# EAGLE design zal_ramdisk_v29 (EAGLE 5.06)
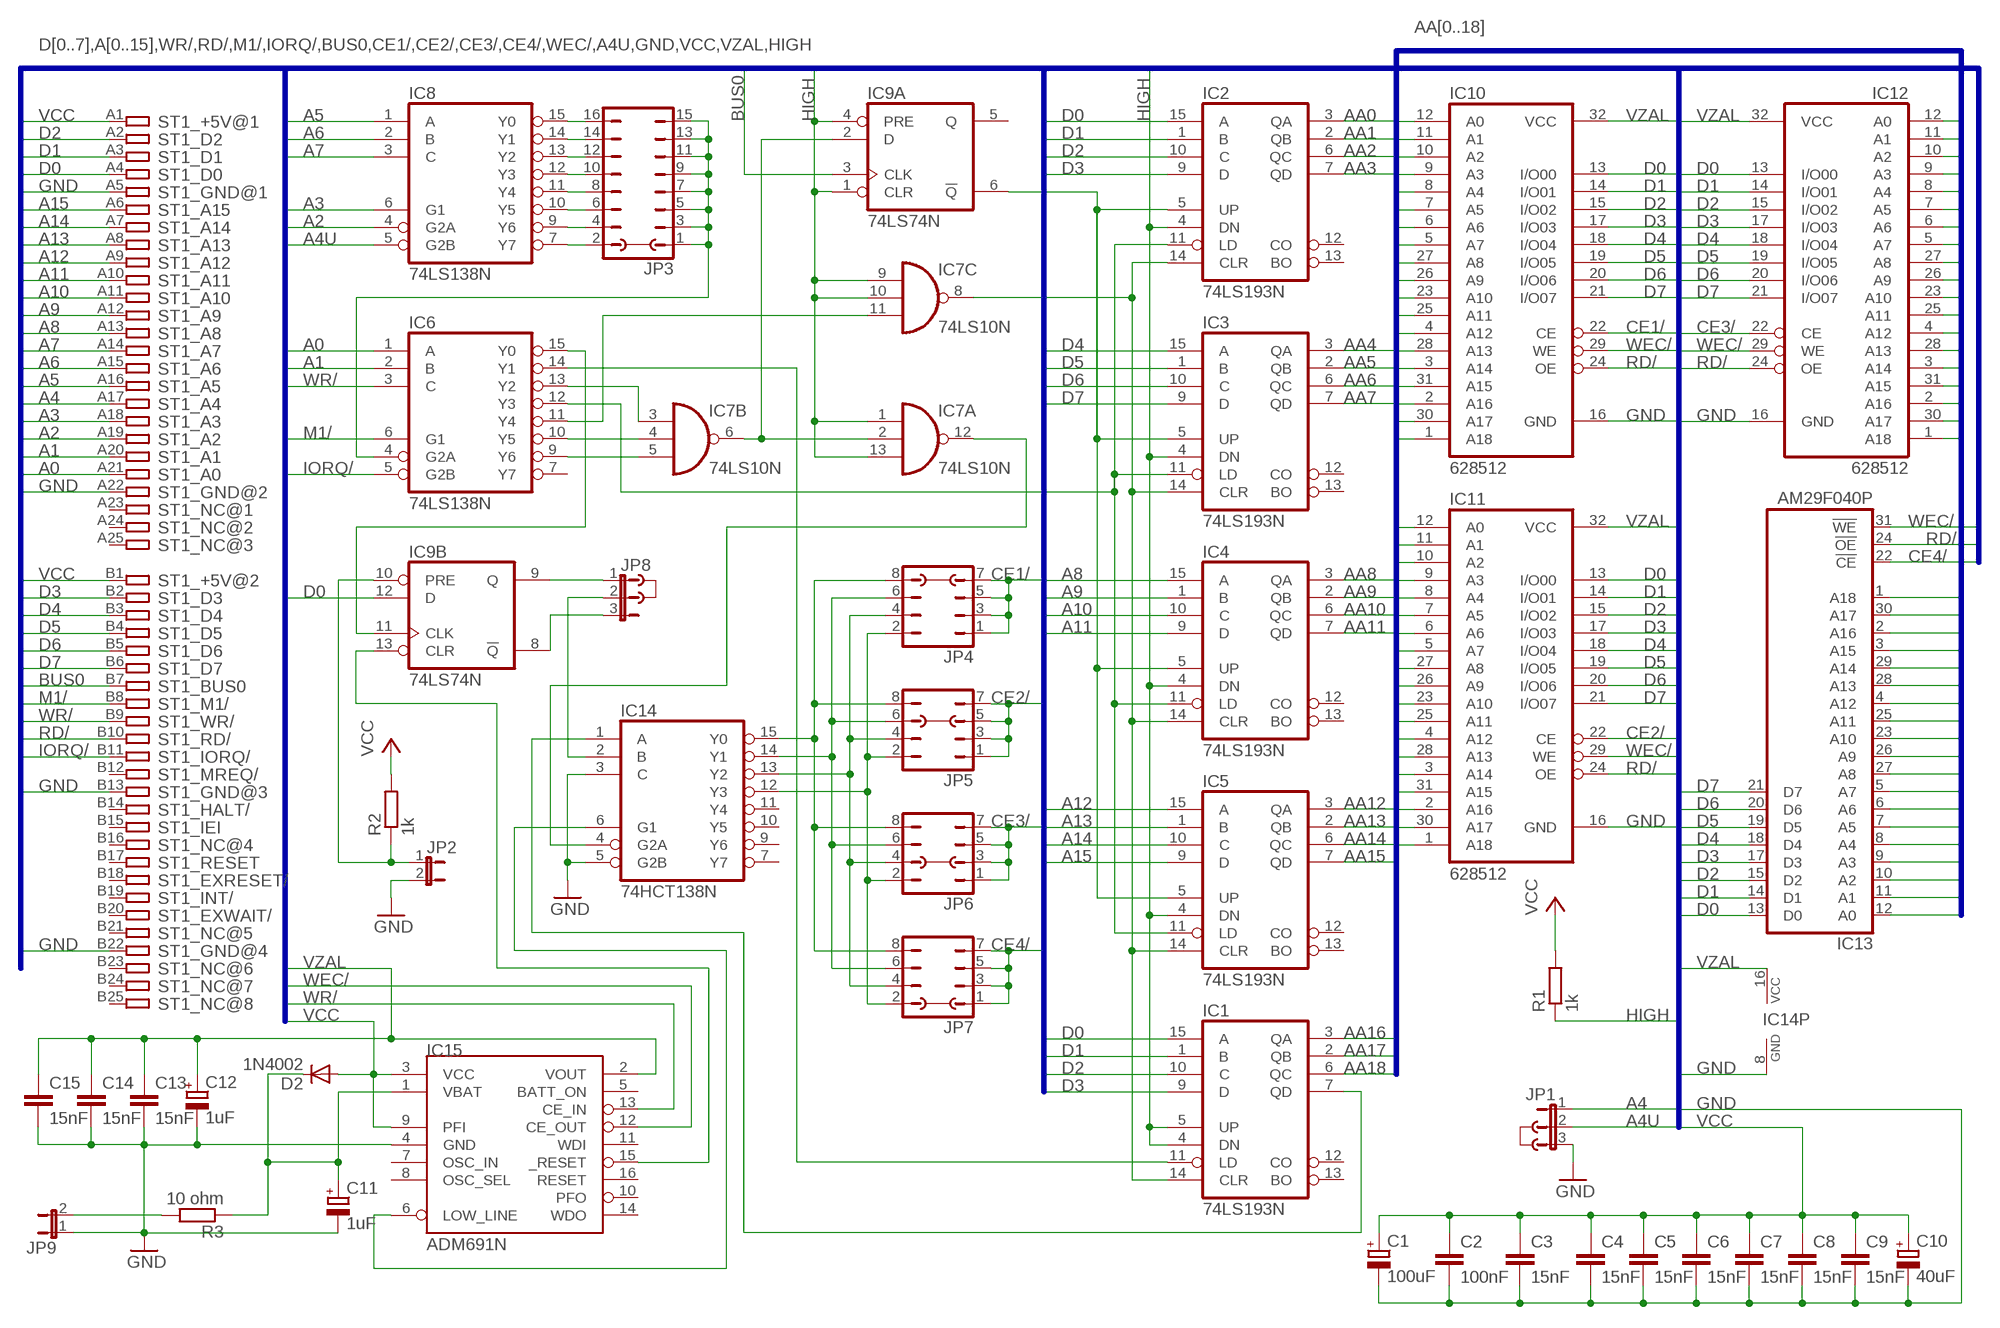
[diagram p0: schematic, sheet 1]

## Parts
C1  100uF  CPOL-EUE2-5  [E2-5]
C2  100nF  C-EU050-024X044  [C050-024X044]
C3  15nF  C-EU050-024X044  [C050-024X044]
C4  15nF  C-EU050-024X044  [C050-024X044]
C5  15nF  C-EU050-024X044  [C050-024X044]
C6  15nF  C-EU050-024X044  [C050-024X044]
C7  15nF  C-EU050-024X044  [C050-024X044]
C8  15nF  C-EU050-024X044  [C050-024X044]
C9  15nF  C-EU050-024X044  [C050-024X044]
C10  40uF  CPOL-EUE2-5  [E2-5]
C11  1uF  CPOL-EUE2-5  [E2-5]
C12  1uF  CPOL-EUE2-5  [E2-5]
C13  15nF  C-EU050-024X044  [C050-024X044]
C14  15nF  C-EU050-024X044  [C050-024X044]
C15  15nF  C-EU050-024X044  [C050-024X044]
D2  1N4002  DIODE-DO41-10  [DO41-10]
IC1  74LS193N  [DIL16]
IC2  74LS193N  [DIL16]
IC3  74LS193N  [DIL16]
IC4  74LS193N  [DIL16]
IC5  74LS193N  [DIL16]
IC6  74LS138N  [DIL16]
IC7  74LS10N  [DIL14]
IC8  74LS138N  [DIL16]
IC9  74LS74N  [DIL14]
IC10  628512  [DIL32]
IC11  628512  [DIL32]
IC12  628512  [DIL32]
IC13  AM29F040P  [DIL32]
IC14  74HCT138N  [DIL16]
IC15  ADM691N  [DIL16]
J1  JUMP-Q  [JUMP]
J3  JUMPER  [JUMP]
J4  JUMP-Q  [JUMP]
J5  JUMP-Q  [JUMP]
J6  JUMP-Q  [JUMP]
J7  JUMP-Q  [JUMP]
J8  JUMPER  [JUMP]
JP1  JP2E  [JP2]
JP2  JP1E  [JP1]
JP3  JP8Q  [JP8Q]
JP4  JP4Q  [JP4Q]
JP5  JP4Q  [JP4Q]
JP6  JP4Q  [JP4Q]
JP7  JP4Q  [JP4Q]
JP8  JP2E  [JP2]
JP9  JP1E  [JP1]
R1  1k  R-EU_0207/7  [0207/7]
R2  1k  R-EU_0207/7  [0207/7]
R3  10 ohm  R-EU_0207/7  [0207/7]
ST1  MZ800BUS  [MZ800BUS]

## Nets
A0: IC6.1(A) ST1.A21
A1: IC6.2(B) ST1.A20
A2: IC8.4(G2A) ST1.A19
A3: IC8.6(G1) ST1.A18
A4: JP1.1 ST1.A17
A4U: IC8.5(G2B) JP1.2
A5: IC8.1(A) ST1.A16
A6: IC8.2(B) ST1.A15
A7: IC8.3(C) ST1.A14
A8: IC4.15(A) ST1.A13
A9: IC4.1(B) ST1.A12
A10: IC4.10(C) ST1.A11
A11: IC4.9(D) ST1.A10
A12: IC5.15(A) ST1.A9
A13: IC5.1(B) ST1.A8
A14: IC5.10(C) ST1.A7
A15: IC5.9(D) ST1.A6
AA0: IC2.3(QA) IC10.12(A0) IC11.12(A0) IC12.12(A0) IC13.12(A0)
AA1: IC2.2(QB) IC10.11(A1) IC11.11(A1) IC12.11(A1) IC13.11(A1)
AA2: IC2.6(QC) IC10.10(A2) IC11.10(A2) IC12.10(A2) IC13.10(A2)
AA3: IC2.7(QD) IC10.9(A3) IC11.9(A3) IC12.9(A3) IC13.9(A3)
AA4: IC3.3(QA) IC10.8(A4) IC11.8(A4) IC12.8(A4) IC13.8(A4)
AA5: IC3.2(QB) IC10.7(A5) IC11.7(A5) IC12.7(A5) IC13.7(A5)
AA6: IC3.6(QC) IC10.6(A6) IC11.6(A6) IC12.6(A6) IC13.6(A6)
AA7: IC3.7(QD) IC10.5(A7) IC11.5(A7) IC12.5(A7) IC13.5(A7)
AA8: IC4.3(QA) IC10.27(A8) IC11.27(A8) IC12.27(A8) IC13.27(A8)
AA9: IC4.2(QB) IC10.26(A9) IC11.26(A9) IC12.26(A9) IC13.26(A9)
AA10: IC4.6(QC) IC10.23(A10) IC11.23(A10) IC12.23(A10) IC13.23(A10)
AA11: IC4.7(QD) IC10.25(A11) IC11.25(A11) IC12.25(A11) IC13.25(A11)
AA12: IC5.3(QA) IC10.4(A12) IC11.4(A12) IC12.4(A12) IC13.4(A12)
AA13: IC5.2(QB) IC10.28(A13) IC11.28(A13) IC12.28(A13) IC13.28(A13)
AA14: IC5.6(QC) IC10.3(A14) IC11.3(A14) IC12.3(A14) IC13.29(A14)
AA15: IC5.7(QD) IC10.31(A15) IC11.31(A15) IC12.31(A15) IC13.3(A15)
AA16: IC1.3(QA) IC10.2(A16) IC11.2(A16) IC12.2(A16) IC13.2(A16)
AA17: IC1.2(QB) IC10.30(A17) IC11.30(A17) IC12.30(A17) IC13.30(A17)
AA18: IC1.6(QC) IC10.1(A18) IC11.1(A18) IC12.1(A18) IC13.1(A18)
BAT3V: C11.+ D2.C IC15.1(VBAT) R3.1
BUS0: IC9.3(A:CLK) ST1.B7
CE1/: IC10.22(CE) JP4.1 JP4.3 JP4.5 JP4.7
CE2/: IC11.22(CE) JP5.1 JP5.3 JP5.5 JP5.7
CE3/: IC12.22(CE) JP6.1 JP6.3 JP6.5 JP6.7
CE4/: IC13.22(!CE) JP7.1 JP7.3 JP7.5 JP7.7
D0: IC1.15(A) IC2.15(A) IC9.12(B:D) IC10.13(I/O00) IC11.13(I/O00) IC12.13(I/O00) IC13.13(D0) ST1.A4
D1: IC1.1(B) IC2.1(B) IC10.14(I/O01) IC11.14(I/O01) IC12.14(I/O01) IC13.14(D1) ST1.A3
D2: IC1.10(C) IC2.10(C) IC10.15(I/O02) IC11.15(I/O02) IC12.15(I/O02) IC13.15(D2) ST1.A2
D3: IC1.9(D) IC2.9(D) IC10.17(I/O03) IC11.17(I/O03) IC12.17(I/O03) IC13.17(D3) ST1.B2
D4: IC3.15(A) IC10.18(I/O04) IC11.18(I/O04) IC12.18(I/O04) IC13.18(D4) ST1.B3
D5: IC3.1(B) IC10.19(I/O05) IC11.19(I/O05) IC12.19(I/O05) IC13.19(D5) ST1.B4
D6: IC3.10(C) IC10.20(I/O06) IC11.20(I/O06) IC12.20(I/O06) IC13.20(D6) ST1.B5
D7: IC3.9(D) IC10.21(I/O07) IC11.21(I/O07) IC12.21(I/O07) IC13.21(D7) ST1.B6
EEE: IC14.2(B) JP8.2
GND [power]: C1.- C2.2 C3.2 C4.2 C5.2 C6.2 C7.2 C8.2 C9.2 C10.- C11.- C12.- C13.2 C14.2 C15.2 IC10.16(GND) IC11.16(GND) IC12.16(GND) IC14.3(C) IC14.5(G2B) IC14.8(GND) IC15.4(GND) JP1.3 JP2.2 JP9.1 ST1.A5 ST1.A22 ST1.B13 ST1.B22
HIGH: IC1.4(DN) IC1.5(UP) IC2.4(DN) IC3.4(DN) IC4.4(DN) IC5.4(DN) IC7.1(A:I0) IC7.9(C:I0) IC7.10(C:I1) IC7.13(A:I2) IC9.1(A:CLR) IC9.4(A:PRE) R1.1
IORQ/: IC6.5(G2B) ST1.B11
M1/: IC6.6(G1) ST1.B8
N$1: IC6.10(Y5) IC7.4(B:I1)
N$2: IC6.9(Y6) IC7.5(B:I2)
N$3: IC6.4(G2A) JP3.1 JP3.3 JP3.5 JP3.7 JP3.9 JP3.11 JP3.13 JP3.15
N$4: IC6.13(Y2) IC7.3(B:I0)
N$5: IC6.11(Y4) IC7.11(C:I2)
N$6: IC7.2(A:I1) IC7.6(B:O) IC9.2(A:D)
N$7: IC8.15(Y0) JP3.16
N$8: IC1.11(LD) IC6.14(Y1)
N$9: IC1.7(QD) IC14.1(A)
N$11: JP9.2 R3.2
N$24: IC2.5(UP) IC3.5(UP) IC4.5(UP) IC5.5(UP) IC9.6(A:!Q)
N$25: IC1.14(CLR) IC2.14(CLR) IC3.14(CLR) IC4.14(CLR) IC5.14(CLR) IC7.8(C:O)
N$26: IC2.11(LD) IC3.11(LD) IC4.11(LD) IC5.11(LD) IC6.12(Y3)
N$31: IC9.9(B:Q) JP8.1
N$34: IC9.13(B:CLR) IC15.15(_RESET)
N$36: IC14.6(G1) IC15.6(LOW_LINE)
N$37: IC6.15(Y0) IC9.11(B:CLK)
N$38: IC7.12(A:O) IC14.4(G2A)
N$39: IC8.14(Y1) JP3.14
N$40: IC8.13(Y2) JP3.12
N$41: IC8.12(Y3) JP3.10
N$42: IC8.11(Y4) JP3.8
N$43: IC8.10(Y5) JP3.6
N$44: IC8.9(Y6) JP3.4
N$45: IC8.7(Y7) JP3.2
N$47: IC9.10(B:PRE) JP2.1 R2.1
N$52: IC14.14(Y1) JP4.6 JP5.6 JP6.6 JP7.6
N$53: IC14.15(Y0) JP4.8 JP5.8 JP6.8 JP7.8
N$54: IC14.13(Y2) JP4.4 JP5.4 JP6.4 JP7.4
N$55: IC14.12(Y3) JP4.2 JP5.2 JP6.2 JP7.2
N$56: IC9.8(B:!Q) JP8.3
RD/: IC10.24(OE) IC11.24(OE) IC12.24(OE) IC13.24(!OE) ST1.B10
VCC [power]: C1.+ C2.1 C3.1 C4.1 C5.1 C6.1 C7.1 C8.1 C9.1 C10.+ D2.A IC15.3(VCC) IC15.9(PFI) R1.2 R2.2 ST1.A1 ST1.B1
VZAL [power]: C12.+ C13.1 C14.1 C15.1 IC10.32(VCC) IC11.32(VCC) IC12.32(VCC) IC14.16(VCC) IC15.2(VOUT)
WEC/: IC10.29(WE) IC11.29(WE) IC12.29(WE) IC13.31(!WE) IC15.12(CE_OUT)
WR/: IC6.3(C) IC15.13(CE_IN) ST1.B9
Unconnected: IC1.12(CO) IC1.13(BO) IC2.12(CO) IC2.13(BO) IC3.12(CO) IC3.13(BO) IC4.12(CO) IC4.13(BO) IC5.12(CO) IC5.13(BO) IC6.7(Y7) IC9.5(A:Q) IC14.7(Y7) IC14.9(Y6) IC14.10(Y5) IC14.11(Y4) IC15.5(BATT_ON) IC15.7(OSC_IN) IC15.8(OSC_SEL) IC15.10(PFO) IC15.11(WDI) IC15.14(WDO) IC15.16(RESET) ST1.A23 ST1.A24 ST1.A25 ST1.B12 ST1.B14 ST1.B15 ST1.B16 ST1.B17 ST1.B18 ST1.B19 ST1.B20 ST1.B21 ST1.B23 ST1.B24 ST1.B25

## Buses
D[0..7],A[0..15],WR/,RD/,M1/,IORQ/,BUS0,CE1/,CE2/,CE3/,CE4/,WEC/,A4U,GND,VCC,VZAL,HIGH
AA[0..18]

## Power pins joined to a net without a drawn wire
GND: IC1.8(GND) IC2.8(GND) IC3.8(GND) IC4.8(GND) IC5.8(GND) IC6.8(GND) IC7.7(P:GND) IC8.8(GND) IC9.7(P:GND) IC13.16(GND)
VCC: IC1.16(VCC) IC2.16(VCC) IC3.16(VCC) IC4.16(VCC) IC5.16(VCC) IC6.16(VCC) IC7.14(P:VCC) IC8.16(VCC) IC9.14(P:VCC) IC13.32(VCC)

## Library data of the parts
C1 C10-C12 = rcl:CPOL-EU: POLARIZED CAPACITOR, European symbol
C2-C9 C13-C15 = rcl:C-EU: CAPACITOR, European symbol
D2 = diode:DIODE-: DIODE
IC1-IC5 = sharp:74*193: Synchronous 4-bit UP/DOWN COUNTER
IC6 IC8 IC14 = 74xx-eu:74*138: 3-line to 8-line DECODER/DEMULTIPLEXER
IC7 = 74xx-eu:74*10: Triple 3-input NAND gate
IC9 = 74xx-eu:74*74: Dual D type positive edge triggered FLIP FLOP, preset and clear
IC10-IC12 = sharp:628512: 4M SRAM 512kword x 8bit
IC13 = sharp:AM29F040: 4-Megabit FLASH MEMORY (512 K x 8 bit) 5 V-only
IC15 = sharp:ADM691: WATCHDOG
J1 J4-J7 = jumper:JUMP-Q: JUMPER header
J3 J8 = jumper:JUMPER: JUMPER header
JP1 JP8 = jumper:JP2E: JUMPER
JP2 JP9 = jumper:JP1E: JUMPER
JP3 = jumper:JP8Q: JUMPER
JP4-JP7 = jumper:JP4Q: JUMPER
R1-R3 = rcl:R-EU_: RESISTOR, European symbol
ST1 = sharp:MZ800BUS: 50-bit BUS for MZ800

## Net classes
0 default: width 0.203 mm
1 power: width 1.143 mm, drill 0.254 mm, clearance 0.381 mm

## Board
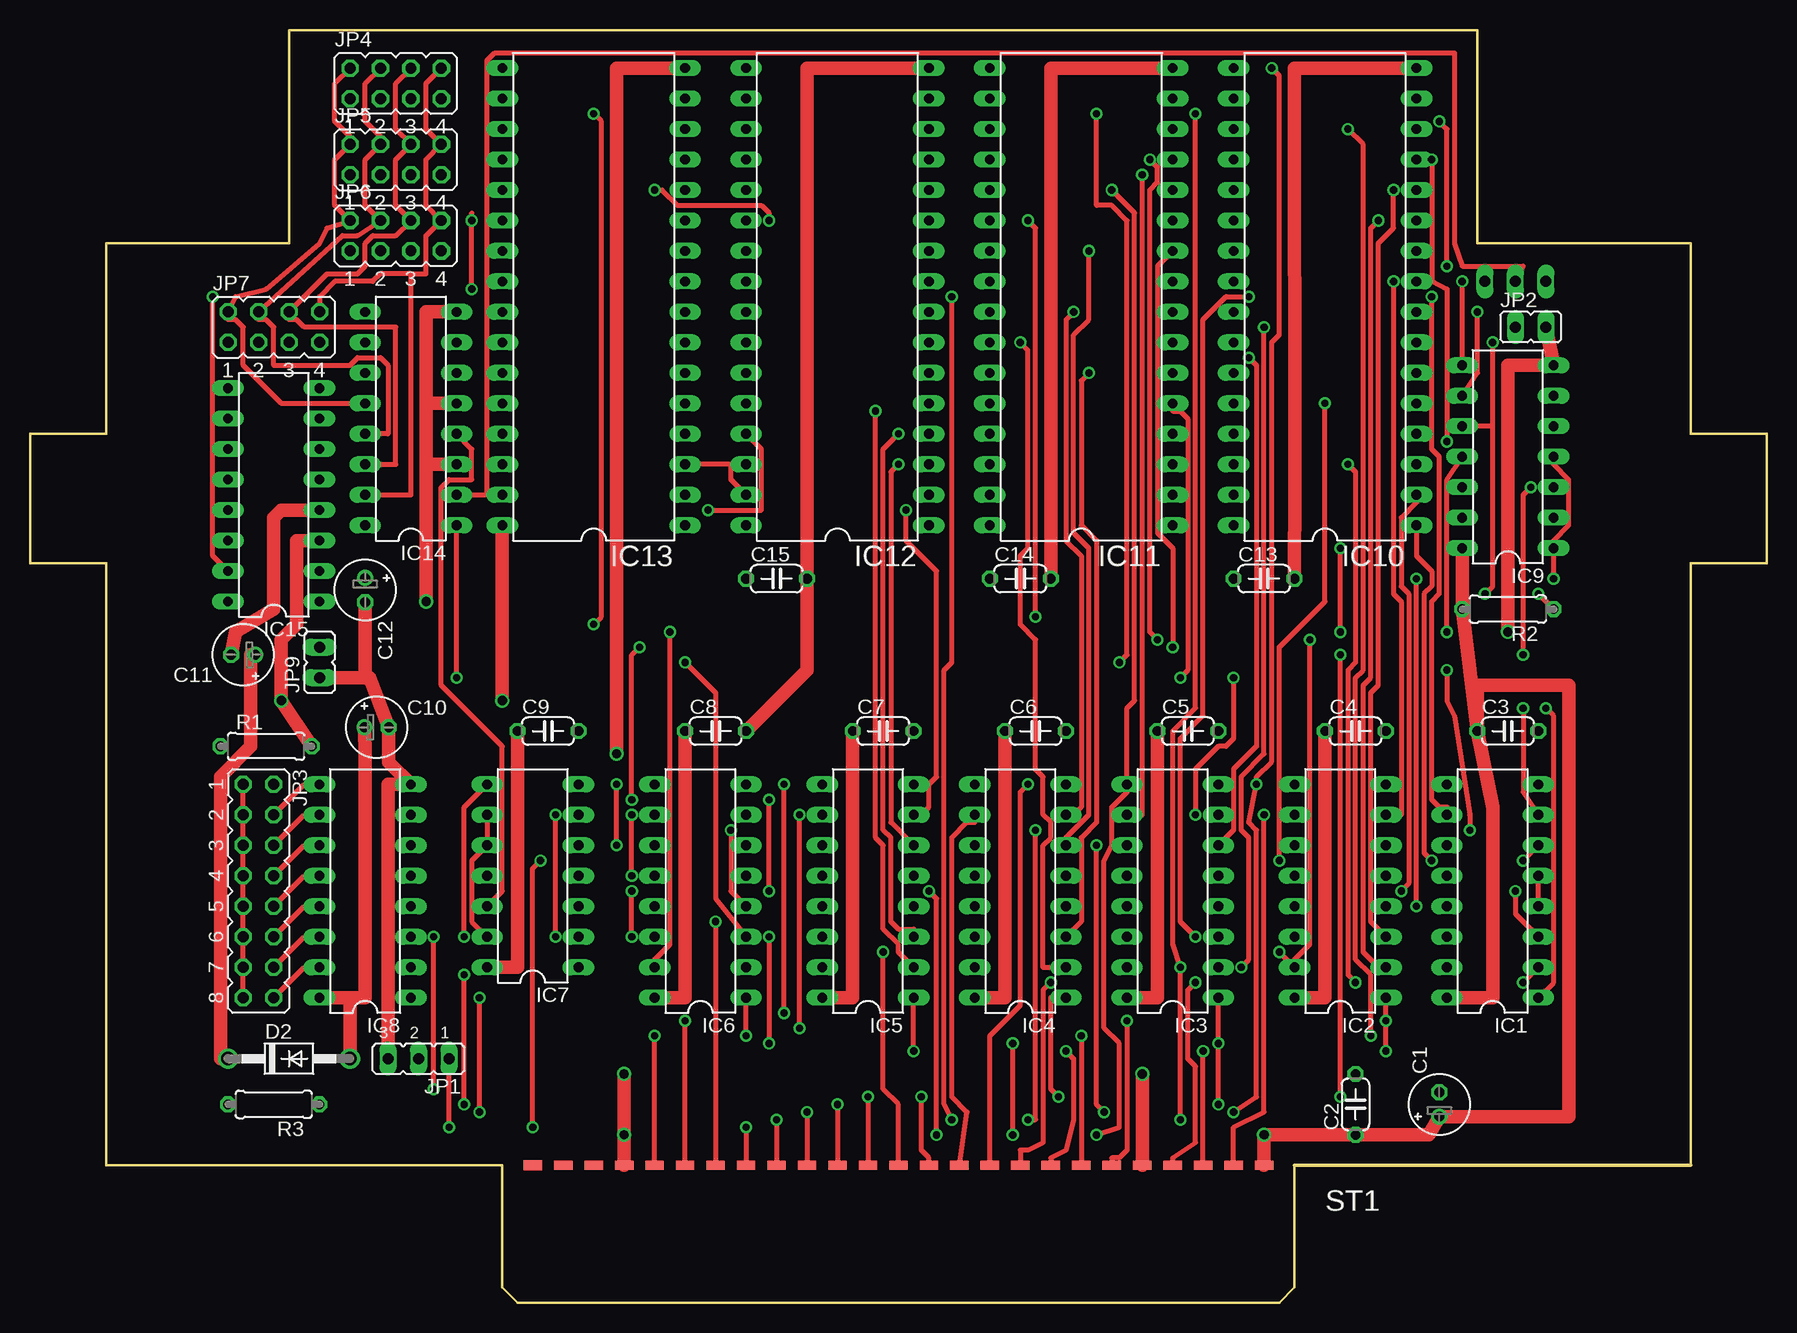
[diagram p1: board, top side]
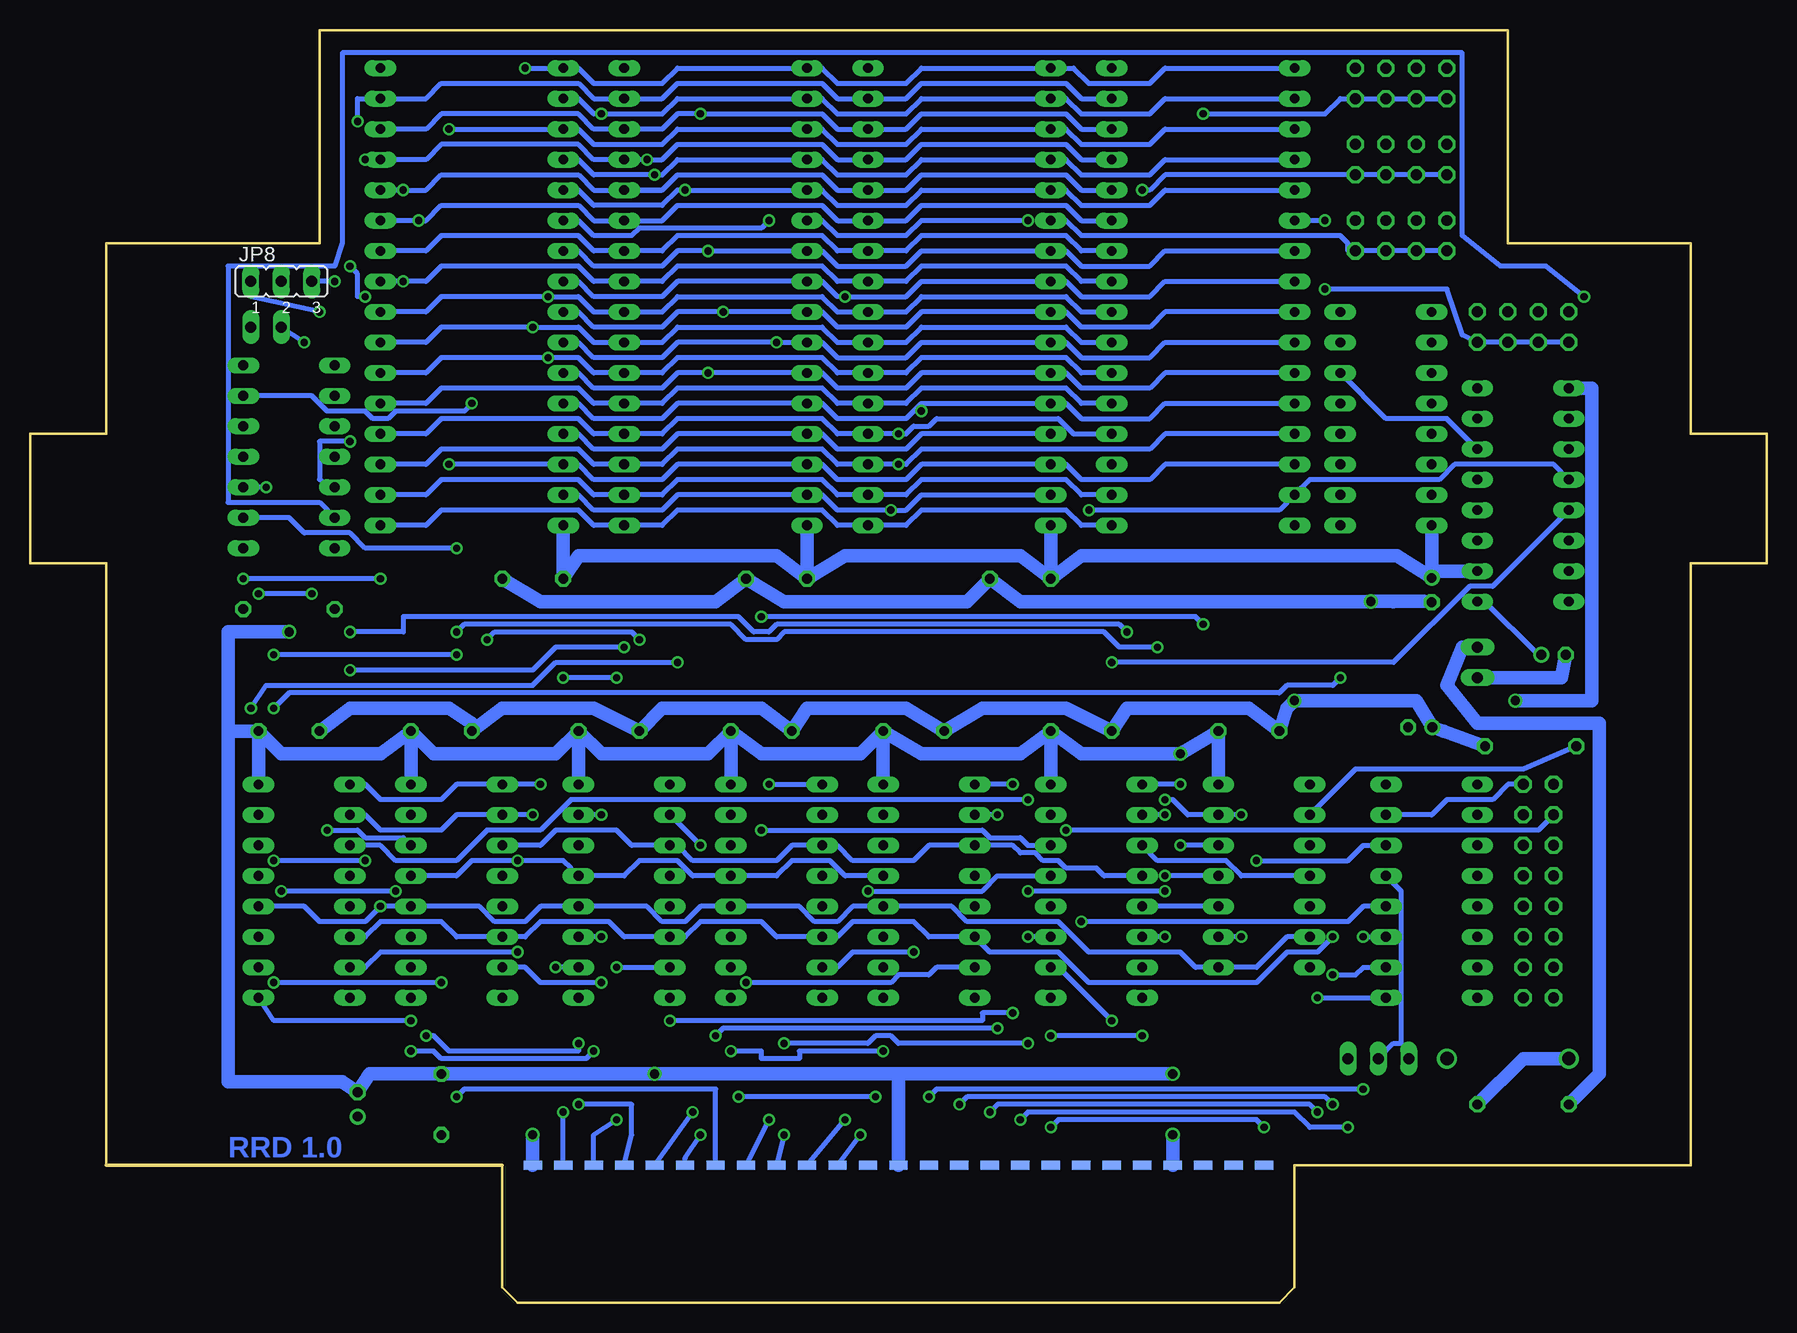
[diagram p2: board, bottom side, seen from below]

Size 144.78 x 106.05 mm. Coordinates in mm from the lower left corner, seen from the top.
Outline: 21.59,88.27 6.35,88.27 6.35,72.39 0,72.39 0,61.59 6.35,61.59 6.35,11.43 39.37,11.43 39.37,1.27 40.64,0 104.14,0 105.41,1.27 105.41,11.43 138.43,11.43 138.43,61.59 144.78,61.59 144.78,72.39 138.43,72.39 138.43,88.27 120.65,88.27 120.65,106.05 21.59,106.05 21.59,88.27
Copper layers (1*16): Top 0.035mm / dielectric 1.5mm / Bottom 0.035mm
Design rules "default *": minimum track width 10mil, minimum drill 22mil, track to track 8mil, track to pad 8mil, pad to pad 8mil, via to via 8mil, smd to smd 8mil, copper to edge 40mil, drill to drill 8mil, minimum pad ring 10mil, minimum via ring 8mil, stop-mask expansion 4mil, vias tented up to drill 0mil, thermal gap 10mil
bKeepout: area 138.4,62.2 to 144.8,72.4
tRestrict: area 38.7,2.5 to 106.7,10.8; area 6.4,11.4 to 13.3,88.3; area 0,62.2 to 6.4,72.4; area 128.9,11.4 to 138.4,88.3; area 138.4,62.2 to 144.8,72.4
bRestrict: area 38.7,2.5 to 106.7,10.8; area 6.4,11.4 to 13.3,88.3; area 0,62.2 to 6.4,72.4; area 128.9,11.4 to 138.4,88.3
vRestrict: area 40.6,10.8 to 104.8,13.3; 3 lines

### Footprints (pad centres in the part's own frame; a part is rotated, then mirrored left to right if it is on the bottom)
E2-5 = drill 0.813 pad 1.27 round: + -1.016,0 | drill 0.813 pad 1.27 octagon: - 1.016,0
C050-024X044 = drill 0.813 octagon: 1 -2.54,0; 2 2.54,0
DO41-10 = drill 1.118 round: A 5.08,0; C -5.08,0
DIL16 = drill 0.813 long: 1 -8.89,-3.81; 2 -6.35,-3.81; 3 -3.81,-3.81; 4 -1.27,-3.81; 5 1.27,-3.81; 6 3.81,-3.81; 7 6.35,-3.81; 8 8.89,-3.81; 9 8.89,3.81; 10 6.35,3.81; 11 3.81,3.81; 12 1.27,3.81; 13 -1.27,3.81; 14 -3.81,3.81; 15 -6.35,3.81; 16 -8.89,3.81
DIL14 = drill 0.813 long: 1 -7.62,-3.81; 2 -5.08,-3.81; 3 -2.54,-3.81; 4 0,-3.81; 5 2.54,-3.81; 6 5.08,-3.81; 7 7.62,-3.81; 8 7.62,3.81; 9 5.08,3.81; 10 2.54,3.81; 11 0,3.81; 12 -2.54,3.81; 13 -5.08,3.81; 14 -7.62,3.81
DIL32 = drill 0.813 long: 1 -17.78,-7.62; 2 -15.24,-7.62; 3 -12.7,-7.62; 4 -10.16,-7.62; 5 -7.62,-7.62; 6 -5.08,-7.62; 7 -2.54,-7.62; 8 0,-7.62; 9 2.54,-7.62; 10 5.08,-7.62; 11 7.62,-7.62; 12 10.16,-7.62; 13 12.7,-7.62; 14 15.24,-7.62; 15 17.78,-7.62; 16 20.32,-7.62; 17 20.32,7.62; 18 17.78,7.62; 19 15.24,7.62; 20 12.7,7.62; 21 10.16,7.62; 22 7.62,7.62; 23 5.08,7.62; 24 2.54,7.62; 25 0,7.62; 26 -2.54,7.62; 27 -5.08,7.62; 28 -7.62,7.62; 29 -10.16,7.62; 30 -12.7,7.62; 31 -15.24,7.62; 32 -17.78,7.62
JP2 = drill 0.914 long: 1 -2.54,0; 2 0,0; 3 2.54,0
JP1 = drill 0.914 long: 1 0,-1.27; 2 0,1.27
JP8Q = drill 0.914 octagon: 1 -8.89,-1.27; 2 -8.89,1.27; 3 -6.35,-1.27; 4 -6.35,1.27; 5 -3.81,-1.27; 6 -3.81,1.27; 7 -1.27,-1.27; 8 -1.27,1.27; 9 1.27,-1.27; 10 1.27,1.27; 11 3.81,-1.27; 12 3.81,1.27; 13 6.35,-1.27; 14 6.35,1.27; 15 8.89,-1.27; 16 8.89,1.27
JP4Q = drill 0.914 octagon: 1 -3.81,-1.27; 2 -3.81,1.27; 3 -1.27,-1.27; 4 -1.27,1.27; 5 1.27,-1.27; 6 1.27,1.27; 7 3.81,-1.27; 8 3.81,1.27
0207/7 = drill 0.813 octagon: 1 -3.81,0; 2 3.81,0
MZ800BUS = smd 1.524 x 0.762: A1 -25.4,7.62; A2 -27.94,7.62; A3 -30.48,7.62; A4 -33.02,7.62; A5 -35.56,7.62; A6 -38.1,7.62; A7 -40.64,7.62; A8 -43.18,7.62; A9 -45.72,7.62; A10 -48.26,7.62; A11 -50.8,7.62; A12 -53.34,7.62; A13 -55.88,7.62; A14 -58.42,7.62; A15 -60.96,7.62; A16 -63.5,7.62; A17 -66.04,7.62; A18 -68.58,7.62; A19 -71.12,7.62; A20 -73.66,7.62; A21 -76.2,7.62; A22 -78.74,7.62; A23 -81.28,7.62; A24 -83.82,7.62 | smd 1.524 x 0.838: A25 -86.36,7.62 | smd 1.524 x 0.762 bottom: B1 -25.4,7.62; B2 -27.94,7.62; B3 -30.48,7.62; B4 -33.02,7.62; B5 -35.56,7.62; B6 -38.1,7.62; B7 -40.64,7.62; B8 -43.18,7.62; B9 -45.72,7.62; B10 -48.26,7.62; B11 -50.8,7.62; B12 -53.34,7.62; B13 -55.88,7.62; B14 -58.42,7.62; B15 -60.96,7.62; B16 -63.5,7.62; B17 -66.04,7.62; B18 -68.58,7.62; B19 -71.12,7.62; B20 -73.66,7.62; B21 -76.2,7.62; B22 -78.74,7.62; B23 -81.28,7.62; B24 -83.82,7.62; B25 -86.36,7.62

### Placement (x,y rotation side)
C1  117.47,16.51 90 top
C2  110.49,16.51 90 top
C3  123.19,47.62 0 top
C4  110.49,47.62 0 top
C5  96.52,47.62 0 top
C6  83.82,47.62 0 top
C7  71.12,47.62 0 top
C8  57.15,47.62 0 top
C9  43.18,47.62 0 top
C10  28.89,47.94 0 top
C11  17.78,53.98 180 top
C12  27.94,59.37 270 top
C13  102.87,60.32 0 top
C14  82.55,60.32 0 top
C15  62.23,60.32 0 top
D2  21.59,20.32 0 top
IC1  121.92,34.29 90 top
IC2  109.22,34.29 90 top
IC3  95.25,34.29 90 top
IC4  82.55,34.29 90 top
IC5  69.85,34.29 90 top
IC6  55.88,34.29 90 top
IC7  41.91,35.56 90 top
IC8  27.94,34.29 90 top
IC9  123.19,70.48 90 top
IC10  107.95,82.55 90 top
IC11  87.63,82.55 90 top
IC12  67.31,82.55 90 top
IC13  46.99,82.55 90 top
IC14  31.75,73.66 90 top
IC15  20.32,67.31 90 top
J1  not placed on the board
J3  not placed on the board
J4  not placed on the board
J5  not placed on the board
J6  not placed on the board
J7  not placed on the board
J8  not placed on the board
JP1  32.38,20.32 180 top
JP2  125.09,81.28 270 top
JP3  19.05,34.29 270 top
JP4  30.48,101.6 0 top
JP5  30.48,95.25 0 top
JP6  30.48,88.9 0 top
JP7  20.32,81.28 0 top
JP8  123.82,85.09 0 bottom
JP9  24.13,53.34 0 top
R1  19.69,46.35 0 top
R2  123.19,57.78 180 top
R3  20.32,16.51 180 top
ST1  128.27,3.81 0 top

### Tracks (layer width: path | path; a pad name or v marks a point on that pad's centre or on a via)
A0  (via drill 0.6)
  Top 0.406: ST1.A21 v52.07,22.22 | v59.69,22.22 IC6.1
  Bottom 0.406: v52.07,22.22 v59.69,22.22
A1  (via drill 0.6)
  Top 0.406: ST1.A20 v54.61,23.49
  Bottom 0.406: v54.61,23.49 59.05,27.94 IC6.2
A2  (via drill 0.6)
  Top 0.406: v57.15,31.75 ST1.A19
  Bottom 0.406: v57.15,31.75 34.93,31.75 33.66,33.02 IC8.4
A3  (via drill 0.6)
  Top 0.406: v59.69,14.61 ST1.A18 | v41.91,14.61 41.91,36.2 v42.55,36.83
  Bottom 0.406: v59.69,14.61 59.05,15.24 42.55,15.24 v41.91,14.61 | v42.55,36.83 34.93,36.83 33.66,38.1 IC8.6
A4  (via drill 0.6)
  Top 0.406: v62.23,15.24 ST1.A17 | v34.93,14.61 JP1.1
  Bottom 0.406: v62.23,15.24 61.6,15.88 39.37,15.88 38.1,14.61 v34.93,14.61
A4U
  Bottom 0.406: IC8.5 30.48,34.29 30.48,21.59 31.12,21.59 JP1.2
A5  (via drill 0.6)
  Top 0.406: v64.77,15.88 ST1.A16 | v37.47,15.88 v37.47,25.4
  Bottom 0.406: v64.77,15.88 64.13,16.51 38.1,16.51 v37.47,15.88 | v37.47,25.4 IC8.1
A6  (via drill 0.6)
  Top 0.406: v67.31,16.51 ST1.A15 | v36.2,16.51 v36.2,27.3
  Bottom 0.406: v67.31,16.51 66.67,17.14 36.83,17.14 v36.2,16.51 | v36.2,27.3 34.29,27.3 33.66,27.94 IC8.2
A7  (via drill 0.6)
  Top 0.406: v69.85,17.14 ST1.A14 | v33.66,17.78 v33.66,30.48
  Bottom 0.406: v69.85,17.14 69.21,17.78 v33.66,17.78 | v33.66,30.48 IC8.3
A8  (via drill 0.6)
  Top 0.406: ST1.A13 72.39,16.51 71.12,17.78 v71.12,29.21
  Bottom 0.406: v71.12,29.21 76.2,29.21 77.47,27.94 IC4.15
A9  (via drill 0.6)
  Top 0.406: 74.29,12.7 v74.29,17.14 | 74.29,12.7 74.29,13.97 | 74.29,12.7 74.29,13.34 | ST1.A12 74.93,12.07 74.29,12.7 | IC4.1 85.09,25.4 85.09,17.78 v85.72,17.14
  Bottom 0.406: v74.29,17.14 v85.72,17.14
A10
  Top 0.406: ST1.A11 78.1,15.88 76.83,17.14 76.83,38.73 78.1,40 78.74,40 IC4.10
A11  (via drill 0.6)
  Top 0.406: v83.18,43.18 82.55,42.55 82.55,24.77 80.01,22.22 ST1.A10
  Bottom 0.406: v83.18,43.18 IC4.9
A12  (via drill 0.6)
  Top 0.406: ST1.A9 82.55,12.7 83.18,12.7 84.45,13.34 84.45,26.04 v85.09,26.67
  Bottom 0.406: v85.09,26.67 73.02,26.67 72.39,27.3 69.85,27.3 69.21,27.94 IC5.15
A13  (via drill 0.6)
  Top 0.406: ST1.A8 85.09,12.07 86.36,12.7 86.99,15.24 86.99,20.32 v86.36,20.95 | v73.66,20.95 IC5.1
  Bottom 0.406: v73.66,20.95 80.64,20.95 80.64,20.32 83.82,20.32 83.82,20.95 v86.36,20.95
A14  (via drill 0.6)
  Top 0.406: v87.63,22.22 ST1.A7 | v64.13,22.86 v64.13,40.64
  Bottom 0.406: v64.13,22.86 86.99,22.86 v87.63,22.22 | v64.13,40.64 IC5.10
A15  (via drill 0.6)
  Top 0.406: v91.44,23.49 91.44,12.7 90.8,12.07 90.17,12.07 ST1.A6 | v62.87,24.13 v62.87,43.18
  Bottom 0.406: v62.87,24.13 65.4,24.13 65.4,23.49 v91.44,23.49 | v62.87,43.18 IC5.9
AA0  (via drill 0.6)
  Top 0.406: IC2.3 111.76,31.75 111.76,50.8 112.39,51.44 112.39,88.27 113.66,89.53 v113.66,92.71
  Bottom 0.406: IC13.12 57.15,92.71 58.42,93.98 70.48,93.98 71.75,92.71 IC12.12 77.47,92.71 78.74,93.98 90.8,93.98 92.07,92.71 | 92.07,92.71 IC11.12 | 92.07,92.71 97.79,92.71 99.06,93.98 110.49,93.98 111.76,92.71 v113.66,92.71 IC10.12
AA1  (via drill 0.6)
  Top 0.406: IC2.2 112.39,27.94 111.12,29.21 111.12,51.44 111.76,52.07 111.76,89.53 v112.39,90.17
  Bottom 0.406: IC13.11 57.15,90.17 58.42,91.44 70.48,91.44 71.75,90.17 IC12.11 77.47,90.17 78.74,91.44 90.8,91.44 92.07,90.17 IC11.11 97.79,90.17 99.06,91.44 110.49,91.44 111.76,90.17 v112.39,90.17 IC10.11
AA2  (via drill 0.6)
  Top 0.406: v120.02,39.37 120.02,40.64 118.74,48.89 118.11,50.16 v118.11,52.7 | v95.25,54.61 95.25,62.86 93.98,64.14 93.98,86.36 IC11.10
  Bottom 0.406: IC13.10 57.15,87.63 58.42,88.9 70.48,88.9 71.75,87.63 IC12.10 77.47,87.63 78.74,88.9 90.8,88.9 92.07,87.63 IC11.10 97.79,87.63 99.06,88.9 110.49,88.9 111.76,87.63 IC10.10 | IC2.6 113.66,38.73 116.84,38.73 117.47,39.37 v120.02,39.37 | v118.11,52.7 102.87,52.7 100.96,54.61 v95.25,54.61
AA3  (via drill 0.6)
  Top 0.406: IC2.7 114.3,40.64 114.3,58.42 113.66,59.05 v113.66,85.09
  Bottom 0.406: IC13.9 57.15,85.09 58.42,86.36 70.48,86.36 71.75,85.09 IC12.9 77.47,85.09 78.74,86.36 90.8,86.36 92.07,85.09 IC11.9 97.79,85.09 99.06,86.36 110.49,86.36 111.76,85.09 v113.66,85.09 IC10.9
AA4  (via drill 0.6)
  Top 0.406: v97.15,30.48 95.88,31.75 95.88,46.99 97.79,48.89 97.79,81.91 99.69,83.82 v101.6,83.82
  Bottom 0.406: IC13.8 57.15,82.55 58.42,83.82 70.48,83.82 71.75,82.55 IC12.8 77.47,82.55 78.74,83.82 90.8,83.82 92.07,82.55 IC11.8 97.79,82.55 99.06,83.82 v101.6,83.82 110.49,83.82 111.76,82.55 IC10.8 | v97.15,30.48 IC3.3
AA5  (via drill 0.6)
  Top 0.406: v100.96,27.94 101.6,28.57 101.6,38.73 100.96,39.37 100.96,43.81 102.87,45.72 v102.87,81.28
  Bottom 0.406: IC13.7 57.15,80.01 58.42,81.28 70.48,81.28 71.75,80.01 IC12.7 77.47,80.01 78.74,81.28 90.8,81.28 92.07,80.01 IC11.7 97.79,80.01 99.06,81.28 v102.87,81.28 110.49,81.28 111.76,80.01 IC10.7 | IC3.2 v100.96,27.94
AA6  (via drill 0.6)
  Top 0.406: IC3.6 100.33,39.37 100.33,44.45 102.23,46.35 102.23,78.11 v101.6,78.74
  Bottom 0.406: IC13.6 57.15,77.47 58.42,78.74 70.48,78.74 71.75,77.47 IC12.6 77.47,77.47 78.74,78.74 90.8,78.74 92.07,77.47 IC11.6 97.79,77.47 99.06,78.74 v101.6,78.74 110.49,78.74 111.76,77.47 IC10.6
AA7  (via drill 0.6)
  Top 0.406: v97.15,40.64 97.15,44.45 99.06,46.35 99.69,46.35 100.33,46.99 v100.33,52.07 | v95.88,52.07 96.52,52.7 96.52,73.66 95.88,74.3 95.25,74.3 IC11.5
  Bottom 0.406: IC13.5 57.15,74.93 58.42,76.2 70.48,76.2 71.75,74.93 IC12.5 77.47,74.93 78.74,76.2 90.8,76.2 92.07,74.93 IC11.5 97.79,74.93 99.06,76.2 110.49,76.2 111.76,74.93 IC10.5 | v97.15,40.64 IC3.7 | v95.88,52.07 v100.33,52.07
AA8  (via drill 0.6)
  Top 0.406: IC4.3 87.63,31.75 87.63,38.73 88.9,40 88.9,63.5 87.63,64.77 87.63,76.83 v88.27,77.47
  Bottom 0.406: IC13.27 50.16,77.47 51.44,76.2 57.15,76.2 58.42,77.47 IC12.27 70.48,77.47 71.75,76.2 77.47,76.2 78.74,77.47 IC11.27 v88.27,77.47 90.8,77.47 92.07,76.2 97.79,76.2 99.06,77.47 IC10.27
AA9  (via drill 0.6)
  Top 0.406: IC4.2 84.45,27.94 84.45,38.1 85.09,38.73 85.09,40 84.45,40.64 84.45,43.81 83.82,44.45 83.82,55.24 82.55,56.52 82.55,62.23 83.18,62.86 83.18,79.38 v82.55,80.01
  Bottom 0.406: IC13.26 50.16,80.01 51.44,78.74 57.15,78.74 58.42,80.01 IC12.26 70.48,80.01 71.75,78.74 77.47,78.74 78.74,80.01 IC11.26 v82.55,80.01 90.8,80.01 92.07,78.74 97.79,78.74 99.06,80.01 IC10.26
AA10  (via drill 0.6)
  Top 0.406: IC4.6 86.36,38.73 88.27,40.64 88.27,62.86 86.99,64.14 86.99,80.64 88.27,81.91 v88.27,87.63
  Bottom 0.406: IC13.23 50.16,87.63 51.44,86.36 57.15,86.36 58.42,87.63 IC12.23 70.48,87.63 71.75,86.36 77.47,86.36 78.74,87.63 IC11.23 v88.27,87.63 90.8,87.63 92.07,86.36 97.79,86.36 99.06,87.63 IC10.23
AA11  (via drill 0.6)
  Top 0.406: IC4.7 86.99,40.64 87.63,41.27 87.63,62.23 86.36,63.5 86.36,81.91 v86.99,82.55
  Bottom 0.406: IC13.25 50.16,82.55 51.44,81.28 57.15,81.28 58.42,82.55 IC12.25 70.48,82.55 71.75,81.28 77.47,81.28 78.74,82.55 IC11.25 v86.99,82.55 90.8,82.55 92.07,81.28 97.79,81.28 99.06,82.55 IC10.25
AA12  (via drill 0.6)
  Top 0.406: IC5.3 73.66,31.12 72.39,31.12 71.75,31.75 71.75,38.73 71.12,39.37 71.12,71.12 v72.39,72.39
  Bottom 0.406: IC10.4 111.76,72.39 110.49,73.66 99.06,73.66 97.79,72.39 IC11.4 92.07,72.39 90.8,73.66 78.74,73.66 77.47,72.39 IC12.4 v72.39,72.39 71.75,72.39 71.12,73.03 69.85,73.03 69.21,73.66 59.05,73.66 57.79,72.39 IC13.4
AA13  (via drill 0.6)
  Top 0.406: IC5.2 72.39,29.21 72.39,29.84 71.12,31.12 71.12,38.1 70.48,38.73 v70.48,74.3
  Bottom 0.406: IC13.28 50.16,74.93 51.44,73.66 57.15,73.66 58.42,74.93 IC12.28 70.48,74.93 71.12,74.3 | 71.12,74.3 71.75,73.66 77.47,73.66 78.74,74.93 IC11.28 90.8,74.93 92.07,73.66 97.79,73.66 99.06,74.93 IC10.28 | v70.48,74.3 71.12,74.3
AA14  (via drill 0.6)
  Top 0.406: IC5.6 71.75,40 71.75,69.22 v72.39,69.85
  Bottom 0.406: IC13.29 50.16,72.39 51.44,71.12 70.48,71.12 71.75,69.85 v72.39,69.85 IC12.3 77.47,69.85 78.74,71.12 90.8,71.12 92.07,69.85 IC11.3 97.79,69.85 99.06,71.12 110.49,71.12 111.76,69.85 IC10.3
AA15  (via drill 0.6)
  Top 0.406: IC5.7 74.29,40.64 74.93,41.27 74.93,43.18 75.56,43.81 75.56,60.96 73.02,63.5 v73.02,66.04 | IC13.3 58.42,69.85 58.42,68.58 IC12.31
  Bottom 0.406: IC12.31 70.48,67.31 71.75,66.04 v73.02,66.04 77.47,66.04 78.74,67.31 IC11.31 90.8,67.31 92.07,66.04 97.79,66.04 99.06,67.31 IC10.31
AA16  (via drill 0.6)
  Top 0.406: IC1.3 123.82,32.38 v123.82,34.29 | v114.3,34.29 114.93,34.92 114.93,59.05 114.3,59.69 114.3,65.41 115.57,66.67 IC10.2
  Bottom 0.406: IC13.2 57.15,67.31 58.42,68.58 70.48,68.58 71.75,67.31 IC12.2 77.47,67.31 78.74,68.58 90.8,68.58 92.07,67.31 IC11.2 97.79,67.31 99.06,68.58 110.49,68.58 111.76,67.31 IC10.2 | v114.3,34.29 v123.82,34.29
AA17  (via drill 0.6)
  Top 0.406: v124.46,26.67 IC1.2 | v110.49,26.67 109.85,27.3 109.85,52.7 110.49,53.34 110.49,69.22 v109.85,69.85
  Bottom 0.406: IC13.30 50.16,69.85 51.44,68.58 57.15,68.58 58.42,69.85 IC12.30 70.48,69.85 71.75,68.58 77.47,68.58 78.74,69.85 IC11.30 90.8,69.85 92.07,68.58 97.79,68.58 99.06,69.85 IC10.30 v109.85,69.85 | v110.49,26.67 v124.46,26.67
AA18  (via drill 0.6)
  Top 0.406: v124.46,36.83 IC1.6 | v116.84,36.83 116.2,37.46 116.2,59.05 116.84,59.69 116.84,60.96 115.57,62.23 IC10.1
  Bottom 0.406: IC10.1 111.76,64.77 110.49,66.04 99.06,66.04 97.79,64.77 IC11.1 92.07,64.77 90.8,66.04 78.74,66.04 77.47,64.77 IC12.1 71.75,64.77 70.48,66.04 58.42,66.04 57.15,64.77 IC13.1 | v116.84,36.83 v124.46,36.83
BAT3V
  Top 0.406: 18.41,53.98 C11.+
  Top 1.143: 18.41,53.98 18.41,46.35 15.88,43.81 15.88,20.32 D2.C
  Bottom 0.406: IC15.1 23.5,58.42 19.05,53.98 C11.+
  Bottom 1.143: R3.1 20.32,20.32 D2.C
BUS0  (via drill 0.6)
  Top 0.406: v109.22,17.14 v109.22,53.98 | v124.46,53.98 124.46,67.31 v125.09,67.94
  Bottom 0.406: ST1.B7 87.63,17.78 108.58,17.78 v109.22,17.14 | v109.22,53.98 v124.46,53.98 | v125.09,67.94 IC9.3
CE1/  (via drill 0.6)
  Top 0.406: v46.99,99.06 47.62,98.42 47.62,57.15 v46.99,56.52 | v83.82,57.15 83.82,89.53 v83.18,90.17
  Bottom 0.406: JP4.1 JP4.3 JP4.5 JP4.7 35.56,100.33 36.83,99.06 v46.99,99.06 | v46.99,56.52 47.62,57.15 v83.82,57.15 | v83.18,90.17 83.82,89.53 93.98,89.53 94.61,88.9 97.79,88.9 99.06,90.17 IC10.22
CE2/  (via drill 0.6)
  Top 0.406: v61.6,90.17 61.6,90.8 60.96,91.44 53.98,91.44 52.7,92.71 v52.07,92.71
  Bottom 0.406: JP5.1 JP5.3 JP5.5 JP5.7 50.16,93.98 51.44,92.71 v52.07,92.71 | IC11.22 78.74,90.17 77.47,88.9 71.75,88.9 70.48,90.17 v61.6,90.17
CE3/
  Bottom 0.406: JP6.1 JP6.3 JP6.5 JP6.7 34.93,87.63 34.93,88.27 35.56,88.9 57.15,88.9 58.42,90.17 IC12.22
CE4/  (via drill 0.6)
  Top 0.406: 36.83,90.8 v36.83,90.17 v36.83,84.45
  Bottom 0.406: JP7.1 JP7.3 JP7.5 JP7.7 25.4,80.64 26.67,84.45 v36.83,84.45 | v36.83,90.17 IC13.22
D0  (via drill 0.6)
  Top 0.406: ST1.A4 95.25,12.07 97.15,13.34 97.15,19.68 96.52,20.32 96.52,26.04 v97.15,26.67 | v104.14,29.21 IC2.15 105.41,28.57 106.68,29.84 v106.68,55.24 | v116.84,95.25 116.84,85.09 118.11,84.45 v118.11,71.75 | v93.34,95.25 93.98,94.61 93.98,93.34 93.34,92.71 93.34,55.88 v93.98,55.24
  Bottom 0.406: IC13.13 57.15,95.25 58.42,96.52 70.48,96.52 71.75,95.25 IC12.13 77.47,95.25 78.74,96.52 90.8,96.52 92.07,95.25 v93.34,95.25 IC11.13 97.79,95.25 99.06,96.52 110.49,96.52 111.76,95.25 IC10.13 v116.84,95.25 | v97.15,26.67 102.23,26.67 103.5,27.94 IC2.15 | v104.14,29.21 115.57,29.21 116.84,27.94 IC1.15 | IC9.12 120.65,68.58 120.65,71.75 v118.11,71.75 | v93.98,55.24 94.61,55.88 106.04,55.88 v106.68,55.24
D1  (via drill 0.6)
  Top 0.406: ST1.A3 v97.79,20.95 | v113.03,20.95 v113.03,23.49 IC2.1 | v126.36,49.53 127,48.89 127,26.67 IC1.1 | v90.8,53.34 91.44,53.98 91.44,90.17 90.17,91.44 88.9,91.44 v88.9,99.06
  Bottom 0.406: IC13.14 57.15,97.79 58.42,99.06 70.48,99.06 71.75,97.79 IC12.14 77.47,97.79 78.74,99.06 v88.9,99.06 90.8,99.06 92.07,97.79 IC11.14 97.79,97.79 99.06,99.06 110.49,99.06 111.76,97.79 IC10.14 | v97.79,20.95 98.42,20.32 110.49,20.32 111.12,20.95 v113.03,20.95 | v126.36,49.53 125.09,51.44 102.87,51.44 100.96,53.34 v90.8,53.34 | v113.03,23.49 124.46,23.49 IC1.1
D2  (via drill 0.6)
  Top 0.406: ST1.A2 100.33,14.61 102.87,15.88 v102.87,40.64 | v118.11,86.36 118.11,97.79 v117.47,98.42 | v116.84,83.82 116.84,71.12 117.47,70.48 117.47,59.05 116.84,58.42 116.84,41.91 117.47,41.27 118.11,41.27 IC1.10
  Bottom 0.406: IC13.15 57.15,100.33 58.42,101.6 70.48,101.6 71.75,100.33 IC12.15 77.47,100.33 78.74,101.6 90.8,101.6 92.07,100.33 IC11.15 97.79,100.33 99.06,101.6 110.49,101.6 111.76,100.33 IC10.15 117.47,100.33 v117.47,98.42 | v102.87,40.64 IC2.10 109.22,40.64 110.49,39.37 115.57,39.37 116.84,40.64 IC1.10 | v118.11,86.36 117.47,85.72 117.47,83.82 v116.84,83.82
D3  (via drill 0.6)
  Top 0.406: v100.33,15.88 102.23,17.14 102.23,39.37 101.6,40 v102.23,43.18 102.23,43.81 103.5,45.09 103.5,80.01 104.14,80.64 104.14,102.23 v103.5,102.87
  Bottom 0.406: IC13.17 50.16,102.87 51.44,101.6 56.52,101.6 57.79,102.87 IC12.17 70.48,102.87 71.75,101.6 77.47,101.6 78.74,102.87 IC11.17 90.8,102.87 92.07,101.6 97.79,101.6 99.06,102.87 IC10.17 v103.5,102.87 | ST1.B2 v100.33,15.88 | v102.23,43.18 IC2.9 109.22,43.18 110.49,41.91 115.57,41.91 116.84,43.18 IC1.9
D4  (via drill 0.6)
  Top 0.406: v95.88,15.24 v95.88,27.94 95.25,29.84 95.25,47.62 97.15,49.53 v97.15,99.06
  Bottom 0.406: IC13.18 50.16,100.33 51.44,99.06 57.15,99.06 58.42,100.33 IC12.18 70.48,100.33 71.75,99.06 77.47,99.06 78.74,100.33 IC11.18 90.8,100.33 92.07,99.06 v97.15,99.06 97.79,99.06 99.06,100.33 IC10.18 | ST1.B3 97.79,13.97 v95.88,15.24 | v95.88,27.94 IC3.15
D5  (via drill 0.6)
  Top 0.406: v99.06,16.51 v99.06,21.59 IC3.1 | v111.76,22.22 111.76,27.3 110.49,28.57 110.49,52.07 111.12,52.7 111.12,96.52 v109.85,97.79
  Bottom 0.406: IC13.19 50.16,97.79 51.44,96.52 57.15,96.52 58.42,97.79 IC12.19 70.48,97.79 71.75,96.52 77.47,96.52 78.74,97.79 IC11.19 90.8,97.79 92.07,96.52 97.79,96.52 99.06,97.79 IC10.19 v109.85,97.79 | ST1.B4 94.61,13.97 94.61,16.51 v99.06,16.51 | v99.06,21.59 99.06,20.95 109.85,20.95 111.12,22.22 v111.76,22.22
D6  (via drill 0.6)
  Top 0.406: v89.53,15.88 88.9,16.51 v88.9,38.1 | IC3.10 92.71,40.64 v92.71,93.98
  Bottom 0.406: IC13.20 50.16,95.25 51.44,93.98 57.15,93.98 58.42,95.25 IC12.20 70.48,95.25 71.75,93.98 77.47,93.98 78.74,95.25 IC11.20 90.8,95.25 92.07,93.98 v92.71,93.98 97.79,93.98 99.06,95.25 IC10.20 | ST1.B5 v89.53,15.88 | v88.9,38.1 IC3.10
D7  (via drill 0.6)
  Top 0.406: v88.9,13.97 90.8,14.61 90.8,21.59 89.53,22.86 89.53,36.83 90.17,38.1 90.17,41.27 91.44,42.55 IC3.9 91.44,49.53 92.07,50.16 92.07,90.8 v90.17,92.71
  Bottom 0.406: IC13.21 50.16,92.71 51.44,91.44 57.15,91.44 58.42,92.71 IC12.21 70.48,92.71 71.75,91.44 77.47,91.44 78.74,92.71 | 78.74,92.71 IC11.21 | 78.74,92.71 v90.17,92.71 90.8,92.71 92.07,91.44 97.79,91.44 99.06,92.71 IC10.21 | ST1.B6 90.17,12.07 v88.9,13.97
EEE
  Top 0.406: IC14.2 38.1,67.31 38.1,103.5 38.73,104.14 118.74,104.14 118.74,88.27 119.38,86.36 124.46,86.36 JP8.2
GND  (via drill 0.76)
  Top 1.143: v92.71,19.05 ST1.A5 | v123.19,55.88 123.19,78.11 IC9.7 JP2.2 | IC12.16 64.77,102.87 C15.2 64.77,52.7 C8.2 | IC11.16 85.09,102.87 C14.2 | IC15.4 20.96,66.04 20.32,65.41 20.32,57.78 17.14,55.88 C11.- | C13.2 105.42,68.2 105.41,102.87 IC10.16 | JP1.3 29.84,43.18 IC8.8 29.91,45.02 C10.- 28.32,52.07 27.94,52.07 | v49.53,19.05 v49.53,13.97 ST1.B22 | IC14.8 33.02,82.55 33.02,74.93 | 33.02,74.93 IC14.5 | 33.02,69.85 IC14.3 | 33.02,69.85 33.02,74.93 | v33.02,58.42 33.02,69.85 | IC13.16 48.9,102.87 v48.9,45.72 | 27.94,52.07 JP9.1 | 27.94,52.07 C12.-
  Bottom 1.143: 128.27,47.62 128.27,18.41 118.74,18.41 C1.- 116.46,19.05 C2.2 v92.71,19.05 72.39,19.05 | C4.2 IC2.8 | C5.2 IC3.8 | C6.2 IC4.8 | C5.2 97.15,45.72 88.27,45.72 C6.2 | C9.2 IC7.7 | C8.2 IC6.8 | C8.2 62.23,45.72 70.48,45.72 C7.2 | C7.2 IC5.8 | C7.2 75.56,45.72 83.82,45.72 C6.2 | 128.27,47.62 128.27,55.88 v123.19,55.88 | C5.2 100.96,45.72 111.12,45.72 C4.2 | C3.2 123.82,45.72 115.57,45.72 C4.2 | C13.2 102.23,58.42 87.63,58.42 C14.2 81.91,58.42 66.67,58.42 C15.2 62.23,58.42 v33.02,58.42 32.6,58.42 | 32.6,58.42 31.12,58.42 | C11.- 17.14,52.07 JP9.1 | v48.9,45.72 C9.2 | v48.9,45.72 57.15,45.72 C8.2 | 72.39,19.05 v49.53,19.05 | v49.53,13.97 ST1.B22 | 72.39,19.05 ST1.B13 | v48.9,45.72 C9.2 | C3.2 128.27,47.62 | C3.2 IC1.8 | 32.6,58.42 28.57,58.42 C12.-
HIGH  (via drill 0.6)
  Top 0.406: IC1.4 IC1.5 | IC9.4 127,69.85 128.27,68.58 128.27,64.77 127,63.5 IC9.1 v127,60.32 | v115.57,33.02 v115.57,60.32 | IC7.9 IC7.10 36.83,36.83 36.83,31.75 IC7.13
  Bottom 0.406: IC1.4 121.92,33.02 120.65,31.75 116.84,31.75 v115.57,33.02 IC2.4 107.31,33.02 106.04,31.75 103.5,31.75 102.23,33.02 IC3.4 93.34,33.02 92.07,31.75 90.17,31.75 88.9,33.02 IC4.4 80.64,33.02 79.38,31.75 77.47,31.75 76.2,33.02 IC5.4 67.94,33.02 66.67,31.75 59.05,31.75 56.52,29.21 48.9,29.21 47.62,27.94 IC7.1 42.55,27.94 40.01,30.48 IC7.13 | v115.57,60.32 v127,60.32 | R1.1 20.32,44.45 34.29,44.45 IC7.9
IORQ/  (via drill 0.6)
  Top 0.406: v75.56,13.97 75.56,33.66 v74.93,34.29
  Bottom 0.406: ST1.B11 v75.56,13.97 | v74.93,34.29 65.4,34.29 64.13,35.56 IC6.5
M1/  (via drill 0.6)
  Top 0.406: v83.18,15.24 83.82,15.24 v83.82,39.37
  Bottom 0.406: ST1.B8 v83.18,15.24 | v83.82,39.37 65.4,39.37 64.77,38.73 62.23,38.73 61.6,38.1 IC6.6
N$1  (via drill 0.6)
  Top 0.406: v50.16,35.56 v50.16,40.64
  Bottom 0.406: v50.16,40.64 IC6.10 | IC7.4 v50.16,35.56
N$2  (via drill 0.6)
  Top 0.406: v48.9,38.1 v48.9,43.18
  Bottom 0.406: v48.9,43.18 IC6.9 | IC7.5 v48.9,38.1
N$3  (via drill 0.6)
  Top 0.406: JP3.15 JP3.13 JP3.11 JP3.9 JP3.7 JP3.5 JP3.3 JP3.1 | IC6.4 58.42,34.29 v58.42,39.37
  Bottom 0.406: v58.42,39.37 19.05,39.37 JP3.3
N$4
  Bottom 0.406: IC7.3 IC6.13
N$5
  Bottom 0.406: IC7.11 43.81,35.56 45.09,36.83 50.8,36.83 IC6.11
N$6  (via drill 0.6)
  Top 0.406: v43.81,30.48 v43.81,40.64 | v109.22,55.88 v109.22,62.86 | v50.8,54.61 50.16,53.98 v50.16,41.91
  Bottom 0.406: v43.81,30.48 IC7.2 | v43.81,40.64 IC7.6 48.26,40.64 49.53,41.91 v50.16,41.91 | IC9.2 123.19,65.41 121.92,64.14 118.11,64.14 116.84,62.86 v109.22,62.86 | v109.22,55.88 108.58,56.52 86.36,56.52 85.09,55.24 82.55,55.24 81.91,55.88 55.24,55.88 53.98,54.61 v50.8,54.61
N$7
  Top 0.406: IC8.15 22.86,27.94 JP3.16
N$8  (via drill 0.6)
  Top 0.406: v61.6,34.29 v61.6,41.91 | v50.16,30.48 v50.16,34.29
  Bottom 0.406: IC1.11 115.57,38.1 114.3,36.83 109.22,36.83 106.68,39.37 102.23,39.37 99.69,41.91 v61.6,41.91 | v50.16,34.29 v61.6,34.29 | v50.16,30.48 IC6.14
N$9  (via drill 0.6)
  Top 0.406: IC1.7 124.46,42.55 v124.46,49.53 | v35.56,52.07 IC14.1
  Bottom 0.406: v124.46,49.53 123.19,50.8 40.64,50.8 40.01,51.44 36.2,51.44 v35.56,52.07
N$11
  Bottom 1.143: R3.2 13.97,19.05 13.97,48.26 24.13,48.26 26.67,51.44 25.4,54.61 JP9.2
N$24  (via drill 0.6)
  Top 0.406: v107.95,74.93 107.95,58.42 104.14,54.61 v104.14,36.83
  Bottom 0.406: IC5.5 76.83,35.56 78.1,36.83 81.28,36.83 82.55,35.56 IC4.5 89.53,35.56 90.8,36.83 93.98,36.83 95.25,35.56 IC3.5 99.69,35.56 99.69,36.2 100.33,36.83 v104.14,36.83 107.95,36.83 109.22,35.56 IC2.5 | IC9.6 121.28,75.56 120.02,74.3 116.84,74.3 116.2,73.66 114.93,73.66 114.3,74.3 108.58,74.3 v107.95,74.93
N$25  (via drill 0.6)
  Top 0.406: IC7.8 36.2,41.27 v36.2,30.48
  Bottom 0.406: IC1.14 116.84,30.48 115.57,31.75 110.49,31.75 109.22,30.48 IC2.14 103.5,30.48 102.23,31.75 96.52,31.75 95.25,30.48 IC3.14 90.17,30.48 88.9,31.75 83.82,31.75 82.55,30.48 IC4.14 77.47,30.48 76.2,31.75 71.12,31.75 69.85,30.48 IC5.14 64.77,29.21 59.05,29.21 56.52,26.67 42.55,26.67 40.01,29.21 37.47,29.21 v36.2,30.48
N$26
  Bottom 0.406: IC6.12 55.24,35.56 55.88,36.2 58.42,36.2 59.05,36.83 60.33,36.83 60.96,37.46 62.23,37.46 62.87,38.1 IC5.11 69.85,38.1 71.12,36.83 76.2,36.83 77.47,38.1 IC4.11 81.28,38.1 82.55,36.83 89.53,36.83 90.8,38.1 IC3.11 94.61,38.1 95.88,39.37 100.96,39.37 102.23,38.1 IC2.11
N$31  (via drill 0.6)
  Top 0.406: IC9.9 120.65,77.47 v120.65,82.55
  Bottom 0.406: v120.65,82.55 126.36,83.82 JP8.1
N$34  (via drill 0.6)
  Top 0.406: IC15.15 15.24,62.23 v15.24,83.82
  Bottom 0.406: v15.24,83.82 18.41,86.36 22.23,86.36 25.4,88.9 25.4,104.14 118.74,104.14 118.74,88.27 119.38,86.36 128.27,86.36 128.27,66.67 120.65,66.67 IC9.13
N$36
  Bottom 0.406: IC15.6 26.67,73.66 31.75,73.66 IC14.6
N$37  (via drill 0.6)
  Top 0.406: IC9.11 118.11,68.58 v118.11,55.88 | v53.34,55.88 53.34,29.84 52.07,28.57 IC6.15
  Bottom 0.406: v118.11,55.88 113.66,55.88 113.66,57.15 85.72,57.15 84.45,55.88 83.18,55.88 82.55,56.52 53.98,56.52 v53.34,55.88
N$38
  Top 0.406: IC7.12 39.37,34.29 39.37,46.35 34.29,51.44 34.29,67.94 34.93,68.58 36.83,68.58 36.83,71.12 IC14.4
N$39
  Top 0.406: IC8.14 22.86,30.48 JP3.14
N$40
  Top 0.406: IC8.13 22.86,33.02 JP3.12
N$41
  Top 0.406: IC8.12 22.86,35.56 JP3.10
N$42
  Top 0.406: IC8.11 22.86,38.1 JP3.8
N$43
  Top 0.406: IC8.10 22.86,40.64 JP3.6
N$44
  Top 0.406: IC8.9 22.86,43.18 JP3.4
N$45
  Bottom 0.406: IC8.7 27.94,40.64 26.67,41.91 22.86,41.91 21.59,43.18 JP3.2
N$47  (via drill 0.6)
  Top 0.406: 121.92,73.03 IC9.10 | 121.92,73.03 v121.92,80.01 | v125.73,59.05 R2.1 | v121.28,59.05 121.92,59.69 121.92,73.03
  Bottom 0.406: v121.92,80.01 JP2.1 | v121.28,59.05 v125.73,59.05
N$52
  Top 0.406: JP4.6 30.48,101.6 30.48,97.79 JP5.6 30.48,95.25 30.48,91.44 JP6.6 30.48,88.9 28.57,88.9 27.94,88.27 27.94,86.36 27.3,85.72 24.77,85.72 JP7.6 21.59,81.91 22.23,81.91 22.86,81.28 30.48,81.28 30.48,69.85 IC14.14
N$53
  Top 0.406: JP4.8 33.02,101.6 33.02,97.79 JP5.8 33.02,95.25 33.02,91.44 JP6.8 33.02,88.9 33.02,85.72 31.75,85.72 | 31.75,85.72 29.21,85.72 28.57,85.09 25.4,85.09 24.13,83.82 JP7.8 | IC14.15 31.75,67.31 31.75,85.72
N$54
  Top 0.406: JP4.4 27.94,101.6 27.94,98.42 29.21,97.16 JP5.4 27.94,95.25 27.94,91.44 JP6.4 27.3,88.9 26.04,88.9 JP7.4 19.05,81.91 19.69,81.91 20.32,81.28 20.32,78.11 26.67,78.11 27.3,78.74 29.21,78.74 29.84,78.11 29.84,72.39 IC14.13
N$55
  Top 0.406: JP4.2 25.4,101.6 25.4,98.42 26.67,97.16 JP5.2 25.4,95.25 25.4,91.44 JP6.2 24.77,89.53 24.13,88.27 19.69,84.45 17.14,83.82 JP7.2 16.51,81.91 17.14,81.91 17.78,81.28 17.78,78.11 20.96,74.93 IC14.12
N$56  (via drill 0.6)
  Top 0.406: IC9.8 v119.38,85.09
  Bottom 0.406: v119.38,85.09 JP8.3
RD/  (via drill 0.6)
  Top 0.406: v76.83,15.24 76.2,16.51 76.2,52.7 76.83,53.34 v76.83,83.82
  Bottom 0.406: IC13.24 50.16,85.09 51.44,83.82 57.15,83.82 58.42,85.09 IC12.24 70.48,85.09 71.75,83.82 v76.83,83.82 77.47,83.82 78.74,85.09 | 78.74,85.09 IC11.24 | 78.74,85.09 90.8,85.09 92.07,83.82 97.79,83.82 99.06,85.09 IC10.24 | ST1.B10 v76.83,15.24
VCC  (via drill 0.76)
  Top 1.143: v102.87,13.97 ST1.B1 v102.87,13.97 | v102.87,13.97 C2.1 116.59,13.97 C1.+ 128.27,15.49 128.27,51.44 120.65,51.44 C3.1 | 26.67,25.4 IC8.16 | 26.67,25.4 27.94,25.4 27.94,45.47 C10.+ | IC4.16 81.28,25.4 C6.1 | IC3.16 93.98,25.4 C5.1 | IC6.16 54.61,25.4 C8.1 | IC5.16 68.58,25.4 C7.1 | IC2.16 107.95,25.4 C4.1 | IC1.16 121.92,25.4 121.92,41.27 C3.1 | IC7.14 40.64,27.94 C9.1 | IC9.14 R2.2 C3.1 | v39.37,50.16 IC13.32 | IC15.3 22.23,63.5 22.23,56.52 20.96,55.24 v20.96,50.16 R1.2 | D2.A 26.67,25.4
  Bottom 1.143: v102.87,13.97 ST1.B1 | C3.1 118.11,49.53 109.85,49.53 107.95,48.26 C4.1 105.41,49.53 97.79,49.53 C5.1 92.07,49.53 83.82,49.53 C6.1 80.01,49.53 71.75,49.53 C7.1 65.4,49.53 58.42,49.53 C8.1 53.34,49.53 43.18,49.53 C9.1 40.01,49.53 v39.37,50.16 29.21,50.16 C10.+ 26.92,47.62 R1.2 | IC15.9 14.61,76.2 14.61,50.16 v20.96,50.16
VZAL
  Bottom 1.143: C15.1 62.23,62.23 76.83,62.23 C14.1 | C14.1 82.55,62.23 99.06,62.23 C13.1 IC10.32 | C14.1 IC11.32 | C15.1 IC12.32 | IC15.2 27.94,60.96 C12.+ | C12.+ IC14.16 | C15.1 57.15,62.23 30.86,62.23 C12.+
WEC/  (via drill 0.6)
  Top 0.406: v56.52,66.04 60.96,66.04 60.96,71.12 IC12.29
  Bottom 0.406: IC12.29 70.48,72.39 71.75,71.12 77.47,71.12 78.74,72.39 IC11.29 90.8,72.39 92.07,71.12 97.79,71.12 99.06,72.39 IC10.29 | IC15.12 17.78,69.85 26.04,69.85 27.3,68.58 38.1,68.58 IC13.31 40.64,66.04 v56.52,66.04
WR/  (via drill 0.6)
  Top 0.406: v61.6,30.48 v61.6,21.59 | v81.91,21.59 v81.91,13.97 | v54.61,53.34 57.15,50.8 57.15,33.66 IC6.3
  Bottom 0.406: v61.6,21.59 72.39,21.59 73.02,22.22 74.29,22.22 74.93,21.59 v81.91,21.59 | IC6.3 v61.6,30.48 | v81.91,13.97 ST1.B9 | IC15.13 22.86,59.69 24.77,59.69 31.12,53.34 v54.61,53.34

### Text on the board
Bottom: RRD 1.0
popiska: RAM ROM DISK V1.0 SUKSOFT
